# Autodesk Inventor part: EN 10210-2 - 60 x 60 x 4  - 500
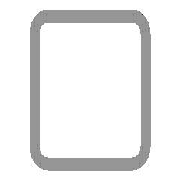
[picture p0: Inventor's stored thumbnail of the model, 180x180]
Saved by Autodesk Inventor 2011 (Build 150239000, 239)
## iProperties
IsCustomPart: 1
Created: 2010-02
Part Number: EN 10210-2 - 60 x 60 x 4  - 500
Material: Steel, Mild
Description: Tube 60*60*4
Document SubType Name: Modeling
Standard: DIN
Designer: PC
Standard Revision: 1997
Standards Organization: DIN
Language: en-US
Size Designation: 60 x 60 x 4
Categories: <MemberInstance><Categories><Category DisplayName="Structural Shapes" InternalName="089c4875-fa83-4c05-b084-43b9cc11f5ed" Mnemonic="GRDR"><CategoryParameter Dis
Stock Number: 60 x 60 x 4
Density: 7.86 g/cm^3
_CCFamilyMember: 20
_CCFamilyDisplayName: DIN EN 10219-2 (Square Hollow Section - Cold Formed) - Cold formed welded structural hollow sections of non-alloy and fine grain structural steel
_FrameMemberDoc: Frame Member File
_Version: 15.0.0
_GetPNFromCC: 1
G_L: 500.000 mm
G_W: 60.000 mm
G_H: 60.000 mm
Author: PC
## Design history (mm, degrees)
node "Start plane"
node "End plane"
sketch "Sketch"
  geometry: L1 (-30, -22)-(-30, 22); L2 (-22, 30)-(22, 30); L3 (30, 22)-(30, -22); L4 (22, -30)-(-22, -30); L5 (-22, 26)-(22, 26); L6 (26, 22)-(26, -22); L7 (22, -26)-(-22, -26); L8 (-26, -22)-(-26, 22); L9 (0, 44.32)-(0, -44.32) reference; L10 (-44.32, 0)-(44.32, 0) reference; A1 r 8 centre (-22, -22) between (-30, -22) and (-22, -30); A2 r 8 centre (-22, 22) between (-22, 30) and (-30, 22); A3 r 8 centre (22, 22) between (30, 22) and (22, 30); A4 r 8 centre (22, -22) between (22, -30) and (30, -22); A5 r 4 centre (-22, 22) between (-22, 26) and (-26, 22); A6 r 4 centre (22, 22) between (26, 22) and (22, 26); A7 r 4 centre (22, -22) between (22, -26) and (26, -22); A8 r 4 centre (-22, -22) between (-26, -22) and (-22, -26)
  constraints: 16 end point, 16 point on circle, 8 centre point, 8 tangent, 4 parallel, 3 equal radius, 2 perpendicular, 7 other
  dimensions: "d7" = 8 radius of A1 (= G_IR); "d10" = 60 distance between parallel lines of L2 L4 (= G_H); "d11" = 60 distance between parallel lines of L1 L3 (= G_W); "d12" = 4 distance between parallel lines of L3 L6 (= G_T); "d15" = 30 distance between parallel lines of L2 L10 (= 0.5 x d10); "d16" = 30 distance between parallel lines of L9 L3 (= 0.5 x d11)
extrude "Body" new body sketch "Sketch" stored distance "d3" = 500 (= G_L); taper "d4" = 0 deg
node "Driven Length"
  sketch "Sketch3"
    geometry: L1 (0, 0)-(10, 0) reference
    constraints: 2 end point, 1 horizontal
  workplane "Work Plane3"
  sketch "Sketch4"
    geometry: L1 (-2, 0)-(12, 0) reference; L2 (-2, 500)-(12, 500) reference
    dimensions: "d18" = 500 distance between parallel lines of L1 L2 (derived)
body "Solid1"
other parameters: "G_W" = 60 [user parameter; used in 1 equation term], "G_H" = 60 [user parameter; used in 1 equation term], "G_T" = 4 [user parameter; used in 1 equation term], "G_IR" = 8 [user parameter; used in 1 equation term], "G_L" = 500 (= d18) [user parameter; used in 1 equation term], "G_OFFSET_START" = 0 [user parameter; used in 1 equation term], "G_OFFSET_END" = 0 [user parameter; used in 1 equation term], "d13" = 0 (computed from G_OFFSET_START), "d17" = 90 deg
